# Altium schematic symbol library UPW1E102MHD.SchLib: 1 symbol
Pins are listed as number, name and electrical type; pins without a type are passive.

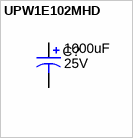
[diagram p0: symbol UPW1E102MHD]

## UPW1E102MHD
designator C?  value 1000uF  Value2Displayed: 25V  (hidden comment: UPW1E102MHD)
CAP, AL, 1000µF, 25V, +/- 20%, Radial; Manufacturer: Nichicon; U/M: EA; Tolerance_%: 20; VDC_V: 25
footprint UPW1E102MHD (12.5Dx20T-5mmLS)
pins: 1 +, 2 -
